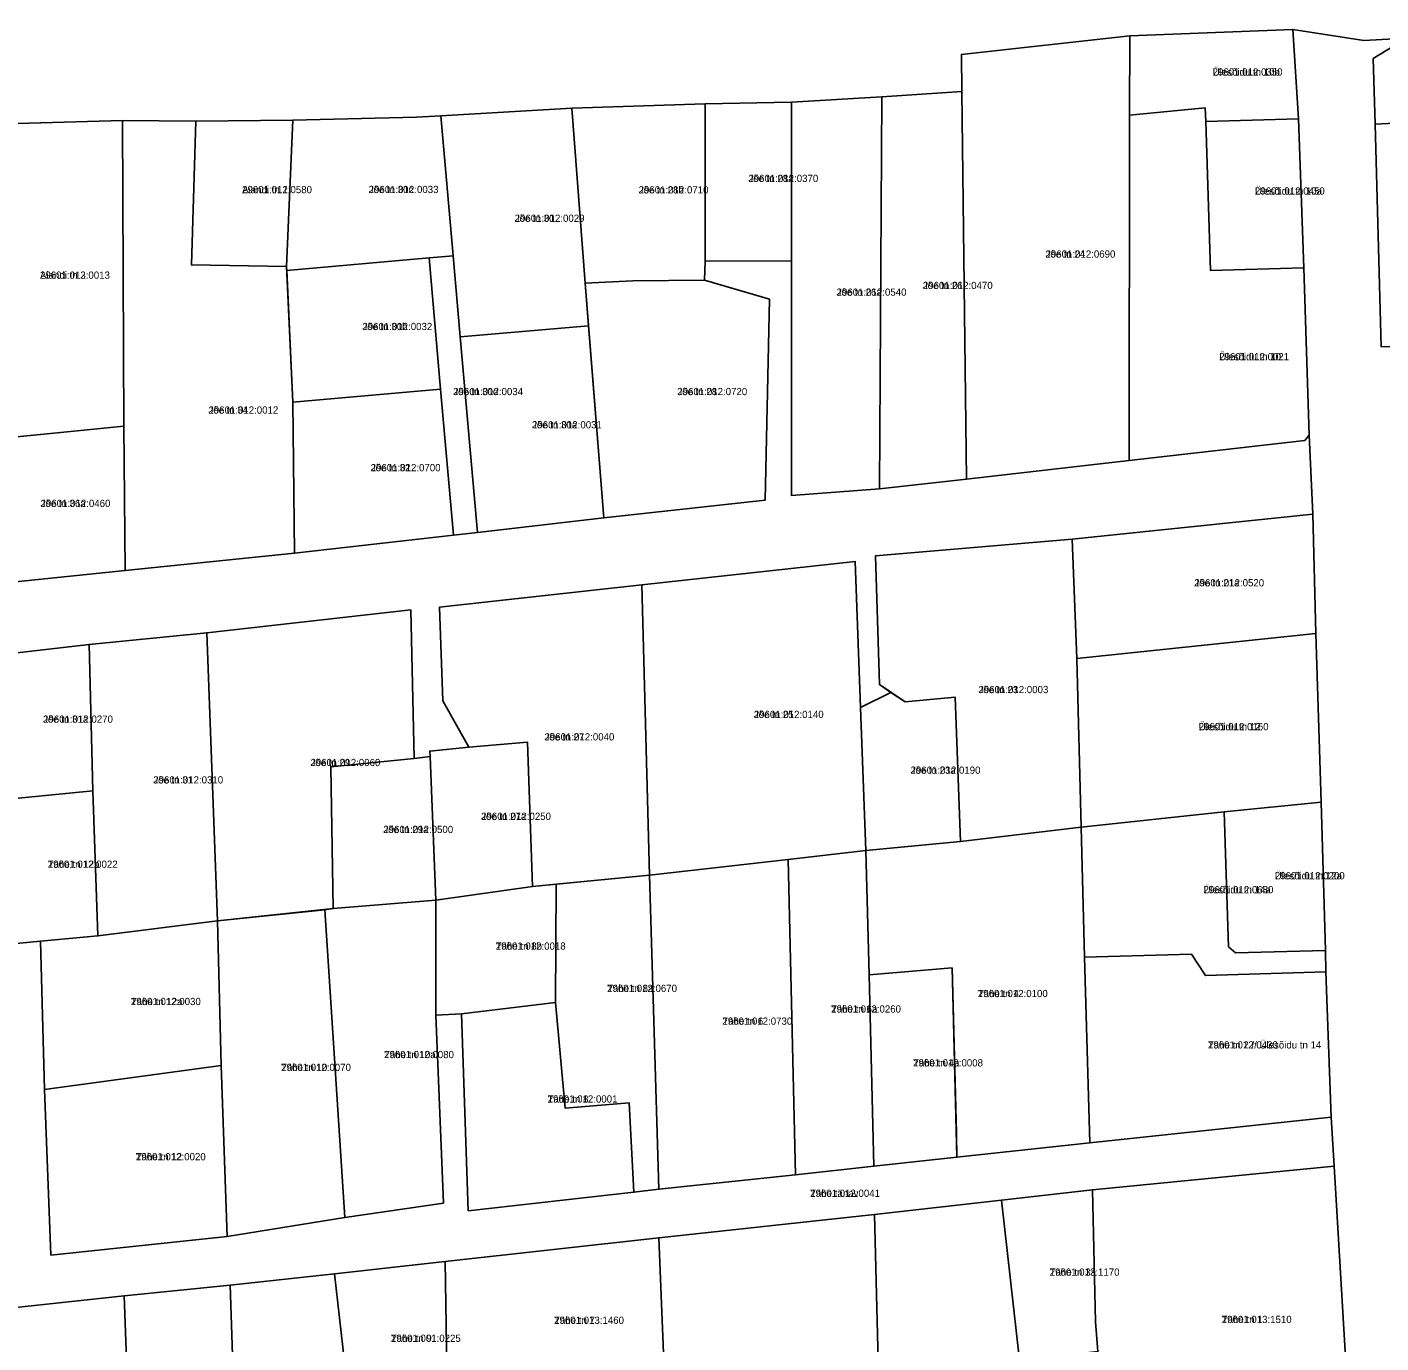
# Model space of a CAD drawing. Extents: x 518839 to 525192, y 6573164 to 6576561.
# Drawn here: x 523959.2 to 524240.2, y 6574008.4 to 6574281.5 of the extents above; entities that cross this region are included whole.
import ezdxf

# ---------------------------------------------------------------- set-up
doc = ezdxf.new("R2010")
doc.units = 0
for name, color, linetype in [('L_AADRESS', 7, 'Continuous'), ('PIIR', 7, 'Continuous'), ('TUNNUS', 7, 'Continuous')]:
    doc.layers.add(name, color=color, linetype=linetype)

msp = doc.modelspace()

# ---------------------------------------------------------------- linework, layer by layer
at = {"layer": 'PIIR'}
for points in [[(524273.82, 6574263.18), (524238.98, 6574261.37), (524238.6, 6574275.01), (524245.54, 6574279.22), (524273.05, 6574281.52)], [(524188.05, 6574279.68), (524188.02, 6574263.26), (524187.93, 6574191.56), (524154.14, 6574187.69), (524153.2, 6574268.14), (524153.11, 6574275.86)], [(524203.73, 6574264.74), (524188.02, 6574263.26), (524188.05, 6574279.68), (524221.89, 6574280.99), (524223.12, 6574262.48), (524203.85, 6574261.94)], [(524136.57, 6574267.06), (524136.08, 6574185.68), (524117.86, 6574184.29), (524117.88, 6574233.04), (524117.88, 6574265.96)], [(524136.57, 6574267.06), (524153.2, 6574268.14), (524154.14, 6574187.69), (524136.08, 6574185.68)], [(524045.04, 6574263.1), (524072.27, 6574264.7), (524075.03, 6574228.35), (524075.73, 6574219.54), (524049.08, 6574217.2), (524047.59, 6574234.07)], [(524099.92, 6574265.57), (524099.95, 6574232.92), (524099.76, 6574228.99), (524084.94, 6574228.84), (524075.03, 6574228.35), (524072.27, 6574264.7)], [(524099.92, 6574265.57), (524117.88, 6574265.96), (524117.88, 6574233.04), (524099.95, 6574232.92)], [(524188.02, 6574263.26), (524203.73, 6574264.74), (524203.85, 6574261.94), (524204.84, 6574230.98), (524224.23, 6574231.58), (524225.34, 6574196.82), (524224.4, 6574195.74), (524187.93, 6574191.56)], [(523978.97, 6574262.1), (523979.23, 6574198.72), (523944.48, 6574195.21), (523944.7, 6574213.27), (523945.07, 6574244.02), (523944.89, 6574261.15)], [(523994.2, 6574262), (523993.26, 6574232.16), (524013.01, 6574231.83), (524014.31, 6574203.64), (524014.66, 6574172.31), (523979.49, 6574168.72), (523979.23, 6574198.72), (523978.97, 6574262.1)], [(523994.2, 6574262), (524014.35, 6574262.2), (524013.01, 6574231.83), (523993.26, 6574232.16)], [(524014.35, 6574262.2), (524040.02, 6574262.81), (524045.04, 6574263.1), (524047.59, 6574234.07), (524042.61, 6574233.63), (524013.05, 6574231.03), (524013.01, 6574231.83)], [(524203.85, 6574261.94), (524223.12, 6574262.48), (524224.23, 6574231.58), (524204.84, 6574230.98)], [(524273.82, 6574263.18), (524274.53, 6574246.16), (524275.17, 6574221.13), (524275.45, 6574215.33), (524240.23, 6574215.18), (524238.98, 6574261.37)], [(524013.05, 6574231.03), (524042.61, 6574233.63), (524045.01, 6574206.35), (524014.31, 6574203.64)], [(524042.61, 6574233.63), (524047.59, 6574234.07), (524049.08, 6574217.2), (524052.64, 6574176.65), (524047.67, 6574176.08), (524045.01, 6574206.35)], [(524084.94, 6574228.84), (524099.76, 6574228.99), (524113.27, 6574225.04), (524112.37, 6574183.31), (524078.88, 6574179.65), (524075.03, 6574228.35)], [(524049.08, 6574217.2), (524075.73, 6574219.54), (524078.88, 6574179.65), (524052.64, 6574176.65)], [(524045.01, 6574206.35), (524047.67, 6574176.08), (524014.66, 6574172.31), (524014.31, 6574203.64)], [(523944.48, 6574195.21), (523979.23, 6574198.72), (523979.49, 6574168.72), (523944.62, 6574165.12)], [(524176.12, 6574175.23), (524226.04, 6574180.4), (524226.68, 6574155.66), (524177.05, 6574150.48)], [(524176.12, 6574175.23), (524177.05, 6574150.48), (524178, 6574115.5), (524152.95, 6574112.51), (524151.82, 6574142.46), (524141.41, 6574141.48), (524136.14, 6574145.05), (524135.31, 6574171.81)], [(524086.76, 6574165.74), (524131.09, 6574170.59), (524132.19, 6574140.3), (524133.28, 6574110.63), (524117.18, 6574108.78), (524088.34, 6574105.47)], [(524063.05, 6574133.1), (524050.89, 6574132.1), (524045.5, 6574141.68), (524044.79, 6574161.13), (524086.76, 6574165.74), (524088.34, 6574105.47), (524064.07, 6574103.15)], [(524039.52, 6574129.74), (524022.2, 6574127.99), (524022.71, 6574098.57), (523998.68, 6574096.05), (523996.46, 6574155.8), (524038.84, 6574160.54)], [(523996.46, 6574155.8), (523998.68, 6574096.05), (523973.87, 6574092.91), (523972.8, 6574123), (523972.03, 6574153.38)], [(524177.05, 6574150.48), (524226.68, 6574155.66), (524227.77, 6574120.68), (524207.68, 6574118.66), (524178, 6574115.5)], [(523972.03, 6574153.38), (523972.8, 6574123), (523953.06, 6574121.1), (523952.16, 6574151.06)], [(524132.19, 6574140.3), (524138.5, 6574143.44), (524141.41, 6574141.48), (524151.82, 6574142.46), (524152.95, 6574112.51), (524133.28, 6574110.63)], [(524042.76, 6574131.26), (524050.89, 6574132.1), (524063.05, 6574133.1), (524064.07, 6574103.15), (524044.01, 6574100.29), (524042.81, 6574130.15)], [(524042.81, 6574130.15), (524044.01, 6574100.29), (524022.71, 6574098.57), (524022.2, 6574127.99), (524039.52, 6574129.74)], [(523953.06, 6574121.1), (523972.8, 6574123), (523973.87, 6574092.91), (523961.94, 6574091.83), (523954.05, 6574091.05), (523953.6, 6574105.96)], [(524178, 6574115.5), (524207.68, 6574118.66), (524208.59, 6574090.65), (524210, 6574089.36), (524228.69, 6574089.84), (524228.78, 6574085.43), (524203.78, 6574084.67), (524200.89, 6574089.1), (524178.69, 6574088.51)], [(524208.59, 6574090.65), (524207.68, 6574118.66), (524227.77, 6574120.68), (524228.69, 6574089.84), (524210, 6574089.36)], [(524151.23, 6574086.3), (524133.98, 6574084.84), (524133.28, 6574110.63), (524152.95, 6574112.51), (524178, 6574115.5), (524178.69, 6574088.51), (524179.8, 6574049.96), (524152.2, 6574046.97)], [(524133.28, 6574110.63), (524133.98, 6574084.84), (524134.97, 6574045.13), (524118.66, 6574043.33), (524117.18, 6574108.78)], [(524088.34, 6574105.47), (524117.18, 6574108.78), (524118.66, 6574043.33), (524090.32, 6574040.32)], [(524088.34, 6574105.47), (524090.32, 6574040.32), (524085.13, 6574039.71), (524084.12, 6574058.27), (524070.89, 6574057.14), (524068.84, 6574079.09), (524069.02, 6574103.62)], [(524044.01, 6574100.29), (524064.07, 6574103.15), (524069.02, 6574103.62), (524068.84, 6574079.09), (524049.31, 6574076.7), (524043.98, 6574076.46)], [(524022.71, 6574098.57), (524044.01, 6574100.29), (524043.98, 6574076.46), (524045.57, 6574037.46), (524025.1, 6574034.42), (524020.96, 6574098.33)], [(523961.94, 6574091.83), (523973.87, 6574092.91), (523998.68, 6574096.05), (523999.48, 6574066.02), (523962.75, 6574061.03)], [(524020.96, 6574098.33), (524025.1, 6574034.42), (524000.7, 6574030.54), (523999.48, 6574066.02), (523998.68, 6574096.05)], [(524178.69, 6574088.51), (524200.89, 6574089.1), (524203.78, 6574084.67), (524228.78, 6574085.43), (524229.88, 6574055.25), (524179.8, 6574049.96)], [(524151.23, 6574086.3), (524152.08, 6574051.99), (524152.2, 6574046.97), (524134.97, 6574045.13), (524133.98, 6574084.84)], [(524049.31, 6574076.7), (524068.84, 6574079.09), (524070.89, 6574057.14), (524084.12, 6574058.27), (524085.13, 6574039.71), (524050.74, 6574035.87)], [(523962.75, 6574061.03), (523999.48, 6574066.02), (524000.7, 6574030.54), (523964.11, 6574026.64)], [(524230.53, 6574045.11), (524234.03, 6573985.67), (524204.44, 6573981.92), (524192.59, 6573980.67), (524183.58, 6573979.74), (524181.45, 6574006.66), (524180.98, 6574012.82), (524180.31, 6574040.22)], [(524161.43, 6574038.08), (524180.31, 6574040.22), (524180.98, 6574012.82), (524181.45, 6574006.66), (524165.16, 6574004.82)], [(524135.05, 6574035.08), (524161.43, 6574038.08), (524165.16, 6574004.82), (524159, 6574004.12), (524159.45, 6573977.4), (524147.65, 6573976.27), (524136.59, 6573974.27)], [(524092.69, 6573970.46), (524091.59, 6573997.82), (524090.29, 6574030.24), (524135.05, 6574035.08), (524136.59, 6573974.27), (524128.09, 6573973.58), (524108.18, 6573971.79), (524099.02, 6573970.97)], [(524046.41, 6573994.52), (524045.92, 6574025.3), (524090.29, 6574030.24), (524091.59, 6573997.82), (524055.99, 6573994.8), (524049.57, 6573994.61)], [(524001.33, 6574020.4), (524022.98, 6574022.77), (524026.43, 6573992.3), (524022.94, 6573991.92), (524002.35, 6573989.41)], [(524026.43, 6573992.3), (524022.98, 6574022.77), (524045.92, 6574025.3), (524046.41, 6573994.52)], [(523986.5, 6573975.48), (523986.02, 6573991.28), (523980.25, 6573991.75), (523979.32, 6574018.22), (524001.33, 6574020.4), (524002.35, 6573989.41), (524003.19, 6573960.61), (523987.11, 6573958.88)], [(523956.21, 6574015.69), (523979.32, 6574018.22), (523980.25, 6573991.75), (523956.97, 6573992.05)]]:
    msp.add_lwpolyline(points, close=True, dxfattribs=at)
for points in [[(524245.54, 6574279.22), (524236.65, 6574278.75), (524221.89, 6574280.99), (524188.05, 6574279.68), (524153.11, 6574275.86), (524153.2, 6574268.14), (524136.57, 6574267.06), (524117.88, 6574265.96), (524099.92, 6574265.57), (524072.27, 6574264.7), (524045.04, 6574263.1), (524040.02, 6574262.81), (524014.35, 6574262.2), (523994.2, 6574262), (523978.97, 6574262.1), (523944.89, 6574261.15), (523564.25, 6574251.27), (523514.93, 6574247.34), (523505.75, 6574246.78), (523443.45, 6574245.11), (523380.3, 6574244.03), (523380.42, 6574240.74), (523212.14, 6574237.55)], [(524234.03, 6573985.67), (524230.53, 6574045.11), (524229.88, 6574055.25), (524228.78, 6574085.43), (524228.69, 6574089.84), (524227.77, 6574120.68), (524226.68, 6574155.66), (524226.04, 6574180.4), (524225.34, 6574196.82), (524224.23, 6574231.58), (524223.12, 6574262.48), (524221.89, 6574280.99), (524236.65, 6574278.75), (524245.54, 6574279.22), (524238.6, 6574275.01), (524238.98, 6574261.37), (524240.23, 6574215.18)], [(523944.62, 6574165.12), (523979.49, 6574168.72), (524014.66, 6574172.31), (524047.67, 6574176.08), (524052.64, 6574176.65), (524078.88, 6574179.65), (524112.37, 6574183.31), (524113.27, 6574225.04), (524099.76, 6574228.99), (524099.95, 6574232.92), (524117.88, 6574233.04), (524117.86, 6574184.29), (524136.08, 6574185.68), (524154.14, 6574187.69), (524187.93, 6574191.56), (524224.4, 6574195.74), (524225.34, 6574196.82), (524226.04, 6574180.4), (524176.12, 6574175.23), (524135.31, 6574171.81), (524136.14, 6574145.05), (524138.5, 6574143.44), (524132.19, 6574140.3), (524131.09, 6574170.59), (524086.76, 6574165.74), (524044.79, 6574161.13), (524045.5, 6574141.68), (524050.89, 6574132.1), (524042.76, 6574131.26), (524042.81, 6574130.15), (524039.52, 6574129.74), (524038.84, 6574160.54), (523996.46, 6574155.8), (523972.03, 6574153.38), (523952.16, 6574151.06)], [(523954.05, 6574091.05), (523961.94, 6574091.83), (523962.75, 6574061.03), (523964.11, 6574026.64), (524000.7, 6574030.54), (524025.1, 6574034.42), (524045.57, 6574037.46), (524043.98, 6574076.46), (524049.31, 6574076.7), (524050.74, 6574035.87), (524085.13, 6574039.71), (524090.32, 6574040.32), (524118.66, 6574043.33), (524134.97, 6574045.13), (524152.2, 6574046.97), (524179.8, 6574049.96), (524229.88, 6574055.25), (524230.53, 6574045.11), (524180.31, 6574040.22), (524161.43, 6574038.08), (524135.05, 6574035.08), (524090.29, 6574030.24), (524045.92, 6574025.3), (524022.98, 6574022.77), (524001.33, 6574020.4), (523979.32, 6574018.22), (523956.21, 6574015.69)]]:
    msp.add_lwpolyline(points, dxfattribs=at)

# ---------------------------------------------------------------- texts
at = {"layer": 'L_AADRESS'}
for s, p in [('Ülesõidu tn 10b', (524205.28, 6574271.46)), ('Jõe tn 28a', (524108.9, 6574249.37)), ('Aiandi tn 1', (524003.8, 6574247.04)), ('Jõe tn 30c', (524030.07, 6574247.07)), ('Jõe tn 28b', (524086.11, 6574246.99)), ('Ülesõidu tn 10a', (524214.04, 6574246.75)), ('Jõe tn 30', (524060.38, 6574241.1)), ('Jõe tn 24', (524170.58, 6574233.67)), ('Aiandi tn 3', (523961.85, 6574229.29)), ('Jõe tn 26', (524145.11, 6574227.15)), ('Jõe tn 26a', (524127.21, 6574225.76)), ('Jõe tn 30b', (524028.77, 6574218.63)), ('Ülesõidu tn 10', (524206.64, 6574212.37)), ('Jõe tn 30d', (524047.62, 6574205.13)), ('Jõe tn 28', (524094.15, 6574205.13)), ('Jõe tn 34', (523996.81, 6574201.29)), ('Jõe tn 30a', (524063.98, 6574198.23)), ('Jõe tn 32', (524030.49, 6574189.33)), ('Jõe tn 36a', (523961.96, 6574181.92)), ('Jõe tn 21a', (524201.46, 6574165.44)), ('Jõe tn 23', (524156.66, 6574143.28)), ('Jõe tn 31a', (523962.48, 6574137.14)), ('Jõe tn 25', (524110.02, 6574138.12)), ('Jõe tn 27', (524066.57, 6574133.46)), ('Ülesõidu tn 12', (524202.38, 6574135.58)), ('Jõe tn 29', (524017.99, 6574128.14)), ('Jõe tn 23a', (524142.57, 6574126.55)), ('Jõe tn 31', (523985.36, 6574124.53)), ('Jõe tn 27a', (524053.41, 6574116.97)), ('Jõe tn 29a', (524033.11, 6574114.25)), ('Tähe tn 12b', (523963.46, 6574107.03)), ('Ülesõidu tn 12a', (524218.18, 6574104.64)), ('Ülesõidu tn 14a', (524203.39, 6574101.74)), ('Tähe tn 8b', (524056.46, 6574090.04)), ('Tähe tn 8a', (524079.58, 6574081.26)), ('Tähe tn 4', (524156.54, 6574080.19)), ('Tähe tn 12a', (523980.72, 6574078.54)), ('Tähe tn 6', (524103.5, 6574074.46)), ('Tähe tn 6a', (524126.07, 6574076.98)), ('Tähe tn 2 // Ülesõidu tn 14', (524204.3, 6574069.53)), ('Tähe tn 10a', (524033.27, 6574067.53)), ('Tähe tn 10', (524011.89, 6574064.86)), ('Tähe tn 4a', (524143.09, 6574065.8)), ('Tähe tn 8', (524067.22, 6574058.3)), ('Tähe tn 12', (523981.74, 6574046.33)), ('Tähe tänav', (524121.71, 6574038.73)), ('Tähe tn 3a', (524171.44, 6574022.37)), ('Tähe tn 1', (524207.17, 6574012.55)), ('Tähe tn 7', (524068.57, 6574012.38)), ('Tähe tn 9', (524034.69, 6574008.64))]:
    msp.add_text(s, height=1.5, dxfattribs=at).set_placement(p)
at = {"layer": 'TUNNUS'}
for s, p in [('29601:012:0350', (524205.28, 6574271.46)), ('29601:012:0370', (524108.9, 6574249.37)), ('29601:012:0580', (524003.8, 6574247.04)), ('29601:012:0033', (524030.07, 6574247.07)), ('29601:012:0710', (524086.11, 6574246.99)), ('29601:012:0450', (524214.04, 6574246.75)), ('29601:012:0029', (524060.38, 6574241.1)), ('29601:012:0690', (524170.58, 6574233.67)), ('29601:012:0013', (523961.85, 6574229.29)), ('29601:012:0470', (524145.11, 6574227.15)), ('29601:012:0540', (524127.21, 6574225.76)), ('29601:012:0032', (524028.77, 6574218.63)), ('29601:012:0021', (524206.64, 6574212.37)), ('29601:012:0034', (524047.62, 6574205.13)), ('29601:012:0720', (524094.15, 6574205.13)), ('29601:012:0012', (523996.81, 6574201.29)), ('29601:012:0031', (524063.98, 6574198.23)), ('29601:012:0700', (524030.49, 6574189.33)), ('29601:012:0460', (523961.96, 6574181.92)), ('29601:012:0520', (524201.46, 6574165.44)), ('29601:012:0003', (524156.66, 6574143.28)), ('29601:012:0270', (523962.48, 6574137.14)), ('29601:012:0140', (524110.02, 6574138.12)), ('29601:012:0040', (524066.57, 6574133.46)), ('29601:012:0160', (524202.38, 6574135.58)), ('29601:012:0060', (524017.99, 6574128.14)), ('29601:012:0190', (524142.57, 6574126.55)), ('29601:012:0310', (523985.36, 6574124.53)), ('29601:012:0250', (524053.41, 6574116.97)), ('29601:012:0500', (524033.11, 6574114.25)), ('29601:012:0022', (523963.46, 6574107.03)), ('29601:012:0200', (524218.18, 6574104.64)), ('29601:012:0680', (524203.39, 6574101.74)), ('29601:012:0018', (524056.46, 6574090.04)), ('29601:012:0670', (524079.58, 6574081.26)), ('29601:012:0100', (524156.54, 6574080.19)), ('29601:012:0030', (523980.72, 6574078.54)), ('29601:012:0730', (524103.5, 6574074.46)), ('29601:012:0260', (524126.07, 6574076.98)), ('29601:012:0430', (524204.3, 6574069.53)), ('29601:012:0080', (524033.27, 6574067.53)), ('29601:012:0070', (524011.89, 6574064.86)), ('29601:012:0008', (524143.09, 6574065.8)), ('29601:012:0001', (524067.22, 6574058.3)), ('29601:012:0020', (523981.74, 6574046.33)), ('29601:012:0041', (524121.71, 6574038.73)), ('29601:013:1170', (524171.44, 6574022.37)), ('29601:013:1460', (524068.57, 6574012.38)), ('29601:013:1510', (524207.17, 6574012.55)), ('29601:001:0225', (524034.69, 6574008.64))]:
    msp.add_text(s, height=1.5, dxfattribs=at).set_placement(p)

doc.saveas('drawing.dxf')
